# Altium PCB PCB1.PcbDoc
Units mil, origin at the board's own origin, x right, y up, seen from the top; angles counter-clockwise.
Board outline 1968 x 1968 mil, 4 copper layers (Top Layer, Internal Plane 1, Internal Plane 2, Bottom Layer), stack 18.2 mil thick; 11 components, 12 nets, 36 pads, 0 vias.
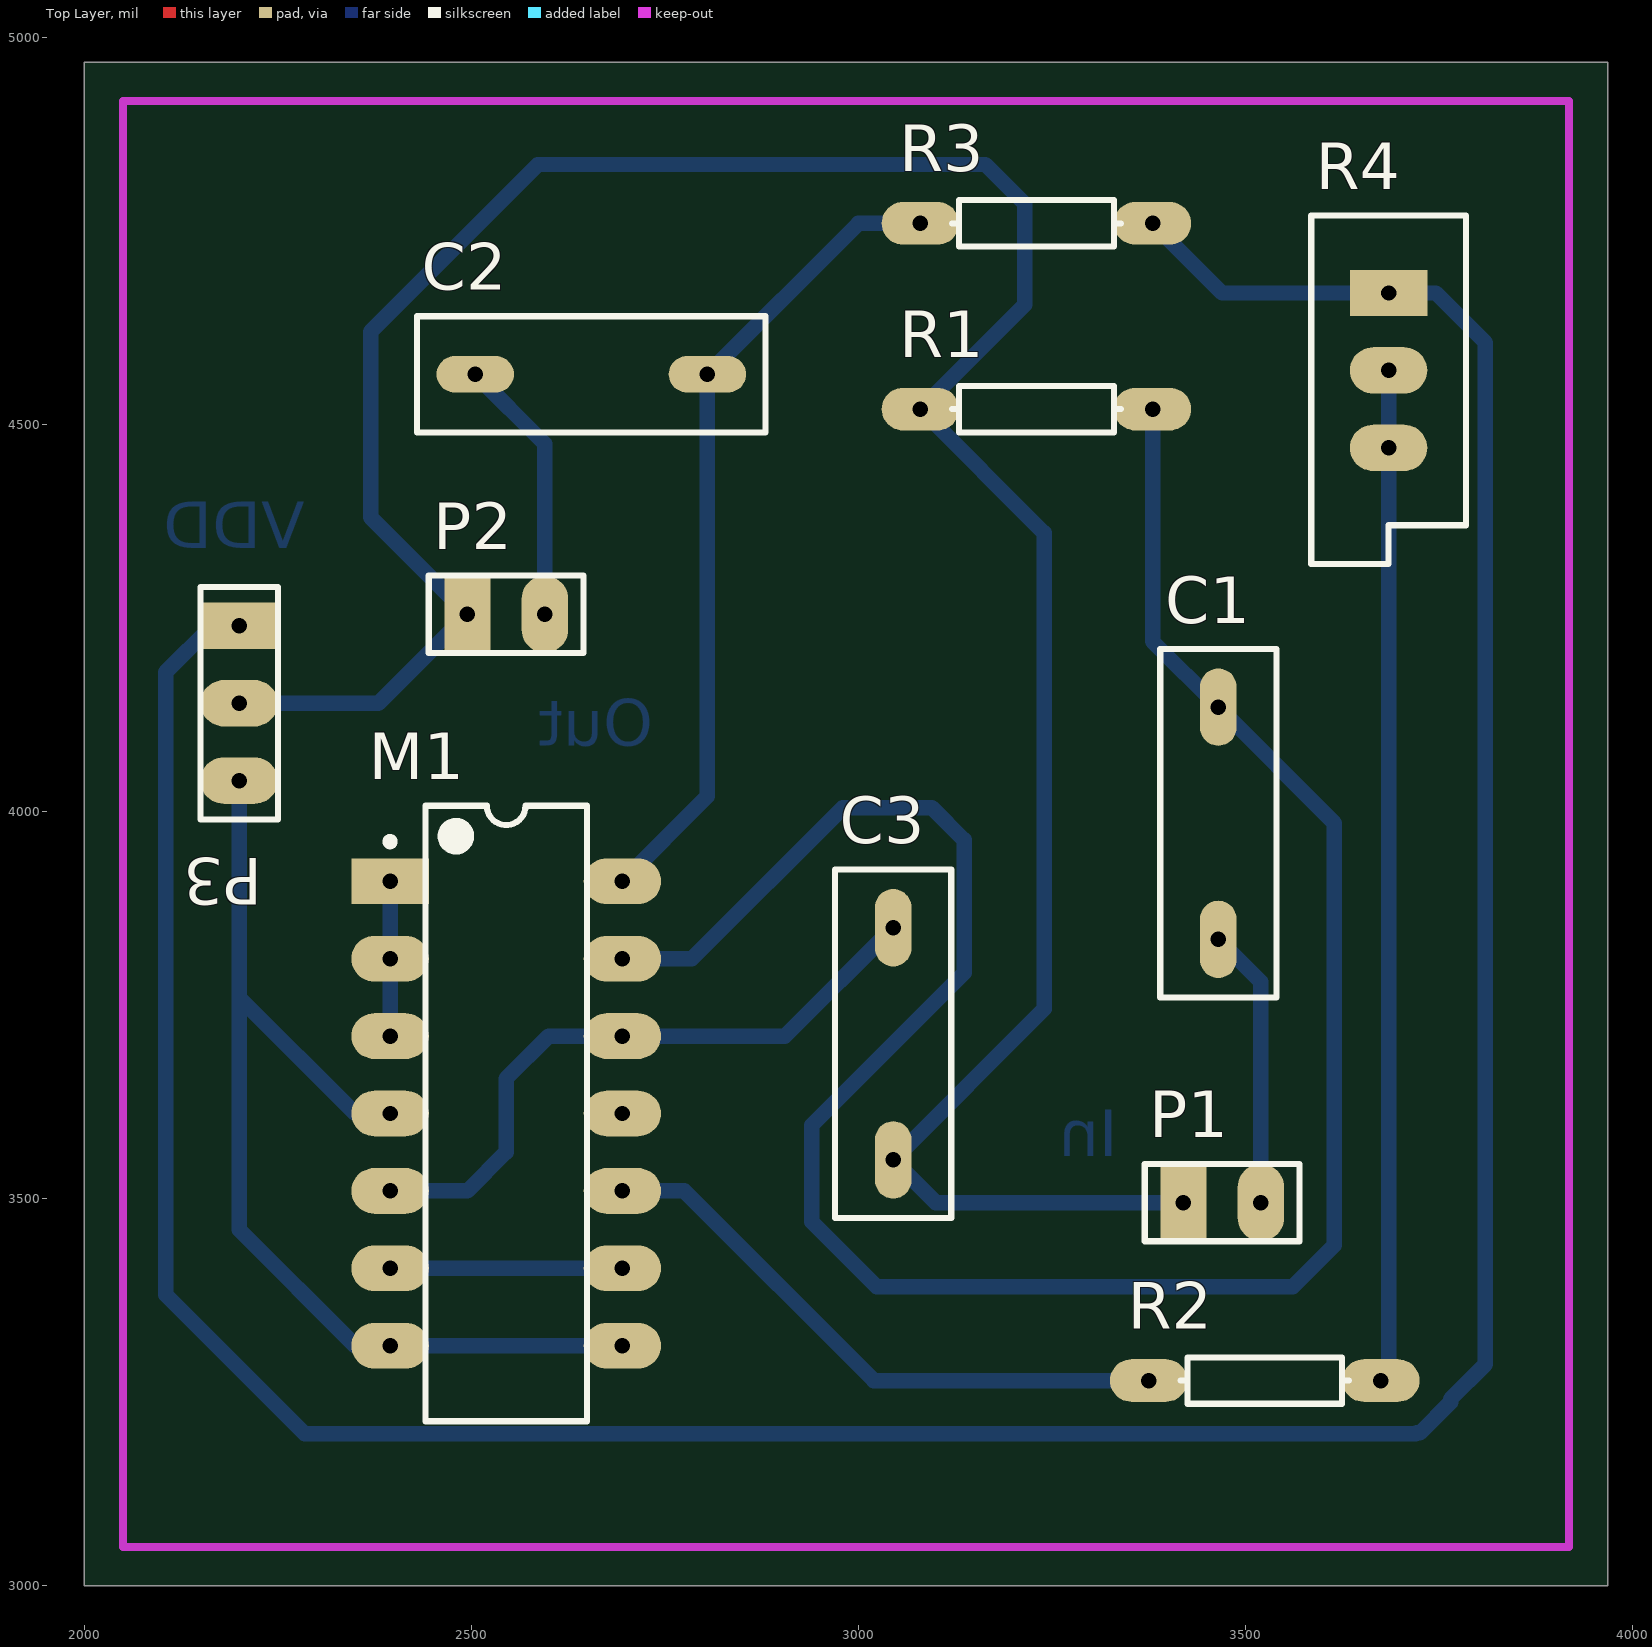
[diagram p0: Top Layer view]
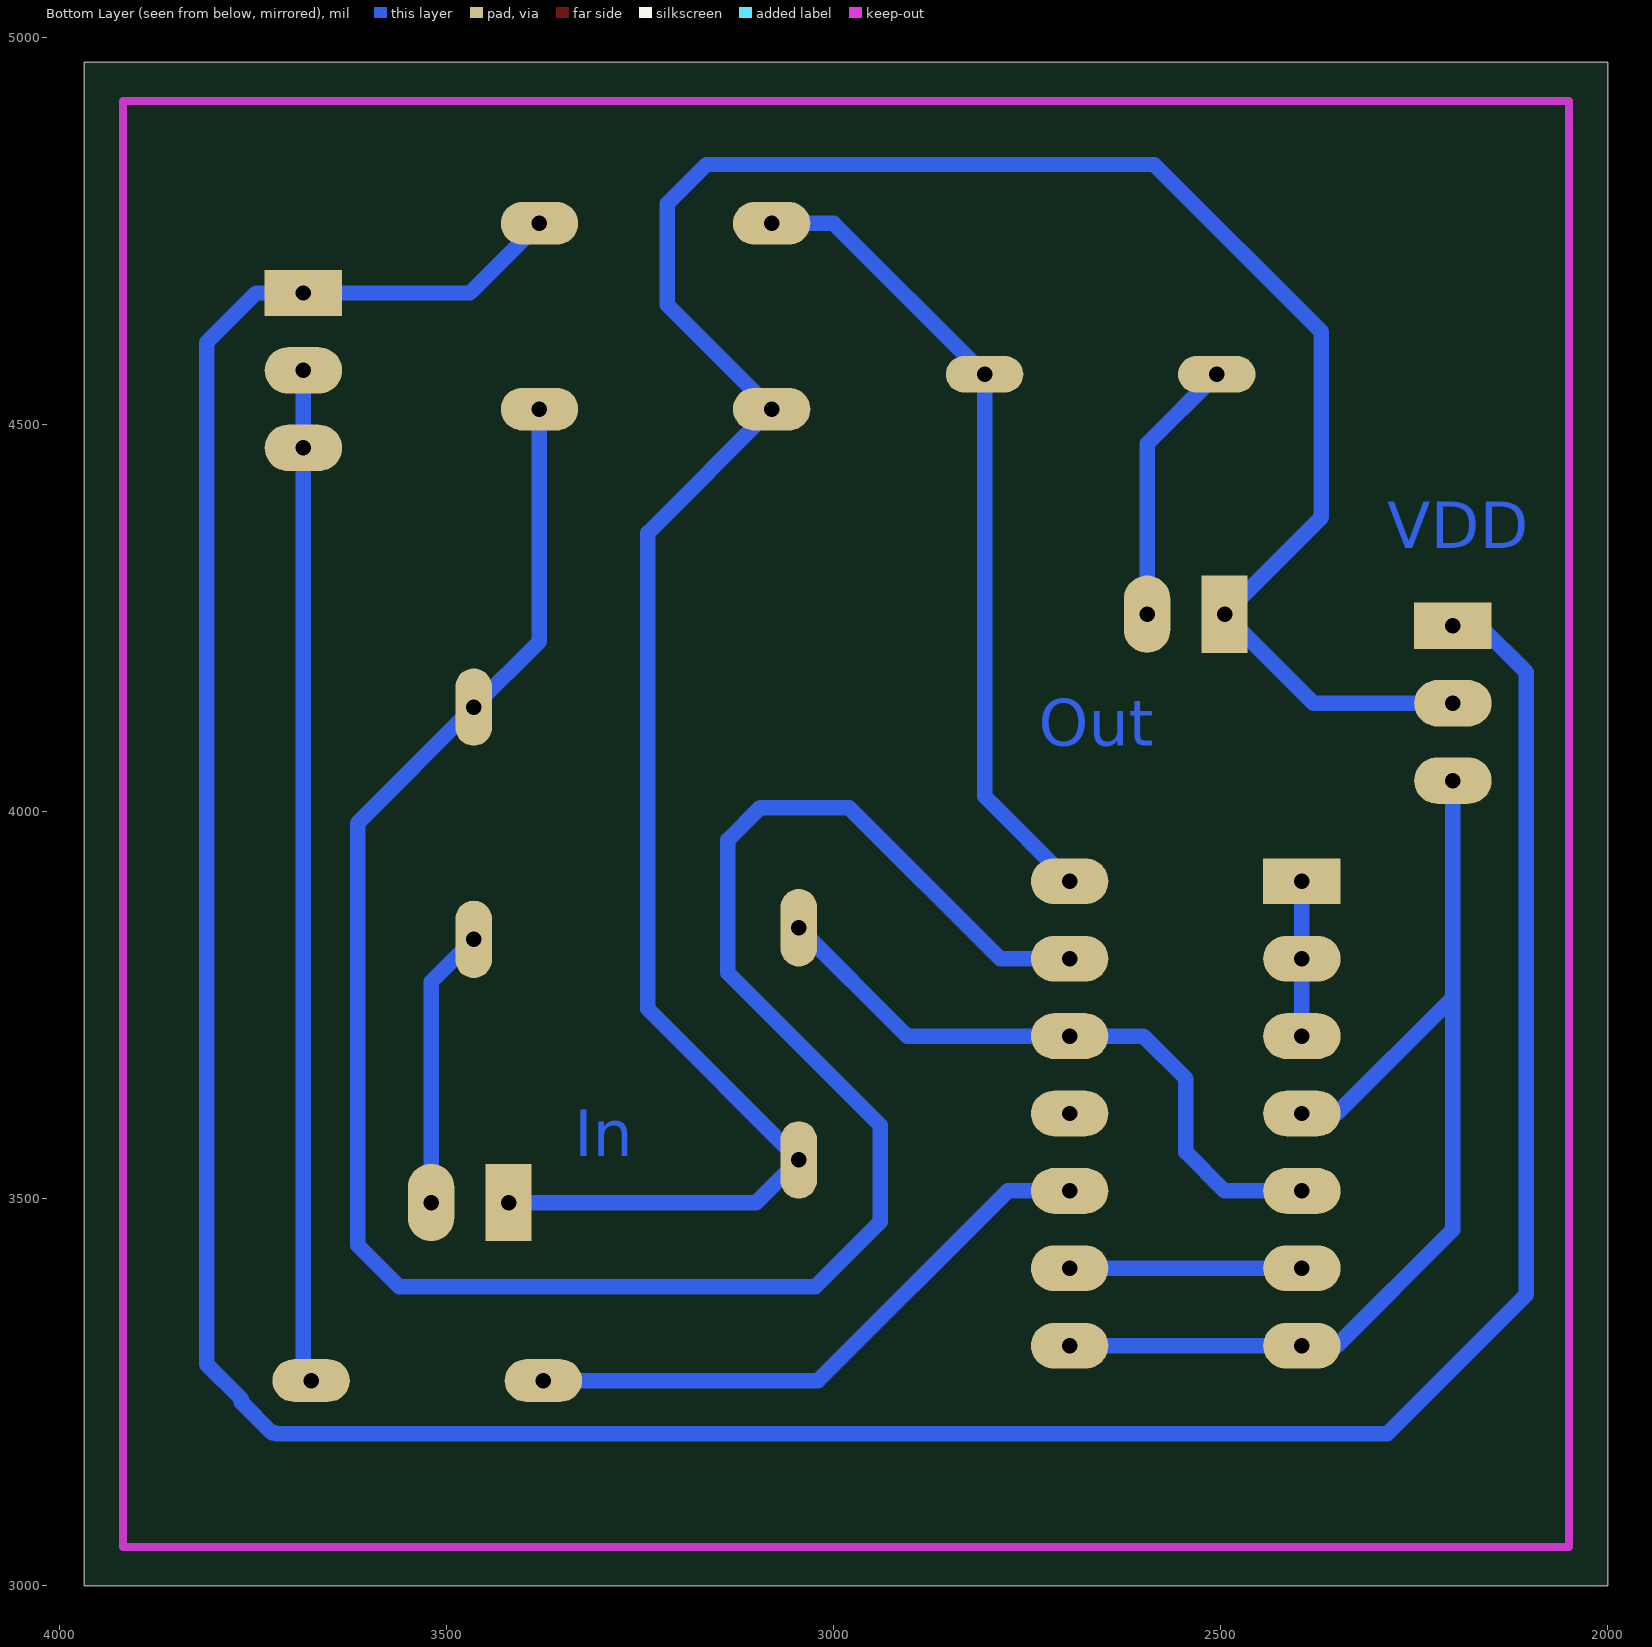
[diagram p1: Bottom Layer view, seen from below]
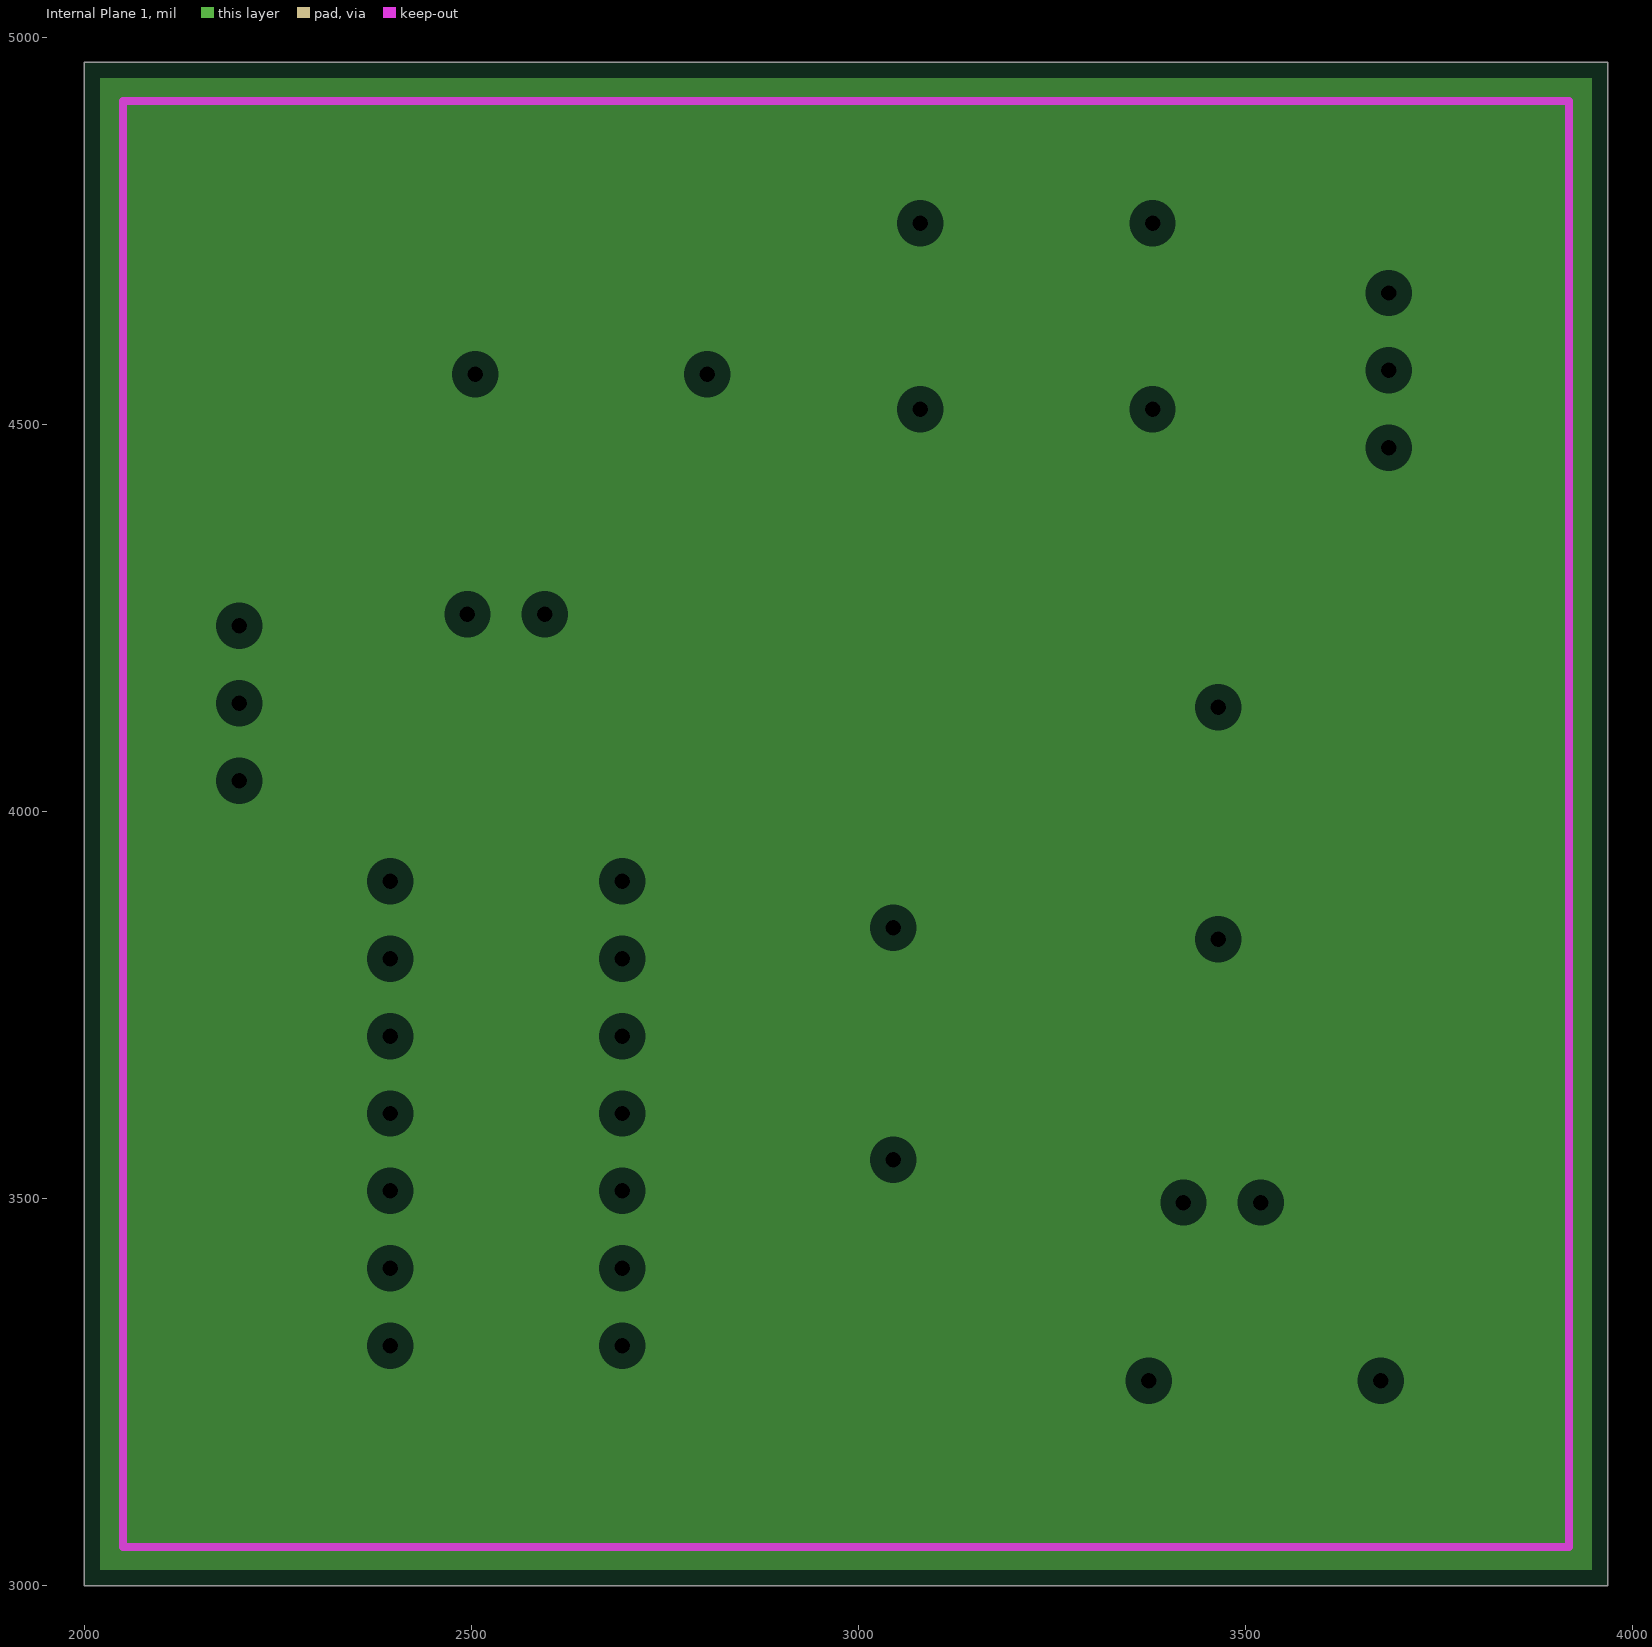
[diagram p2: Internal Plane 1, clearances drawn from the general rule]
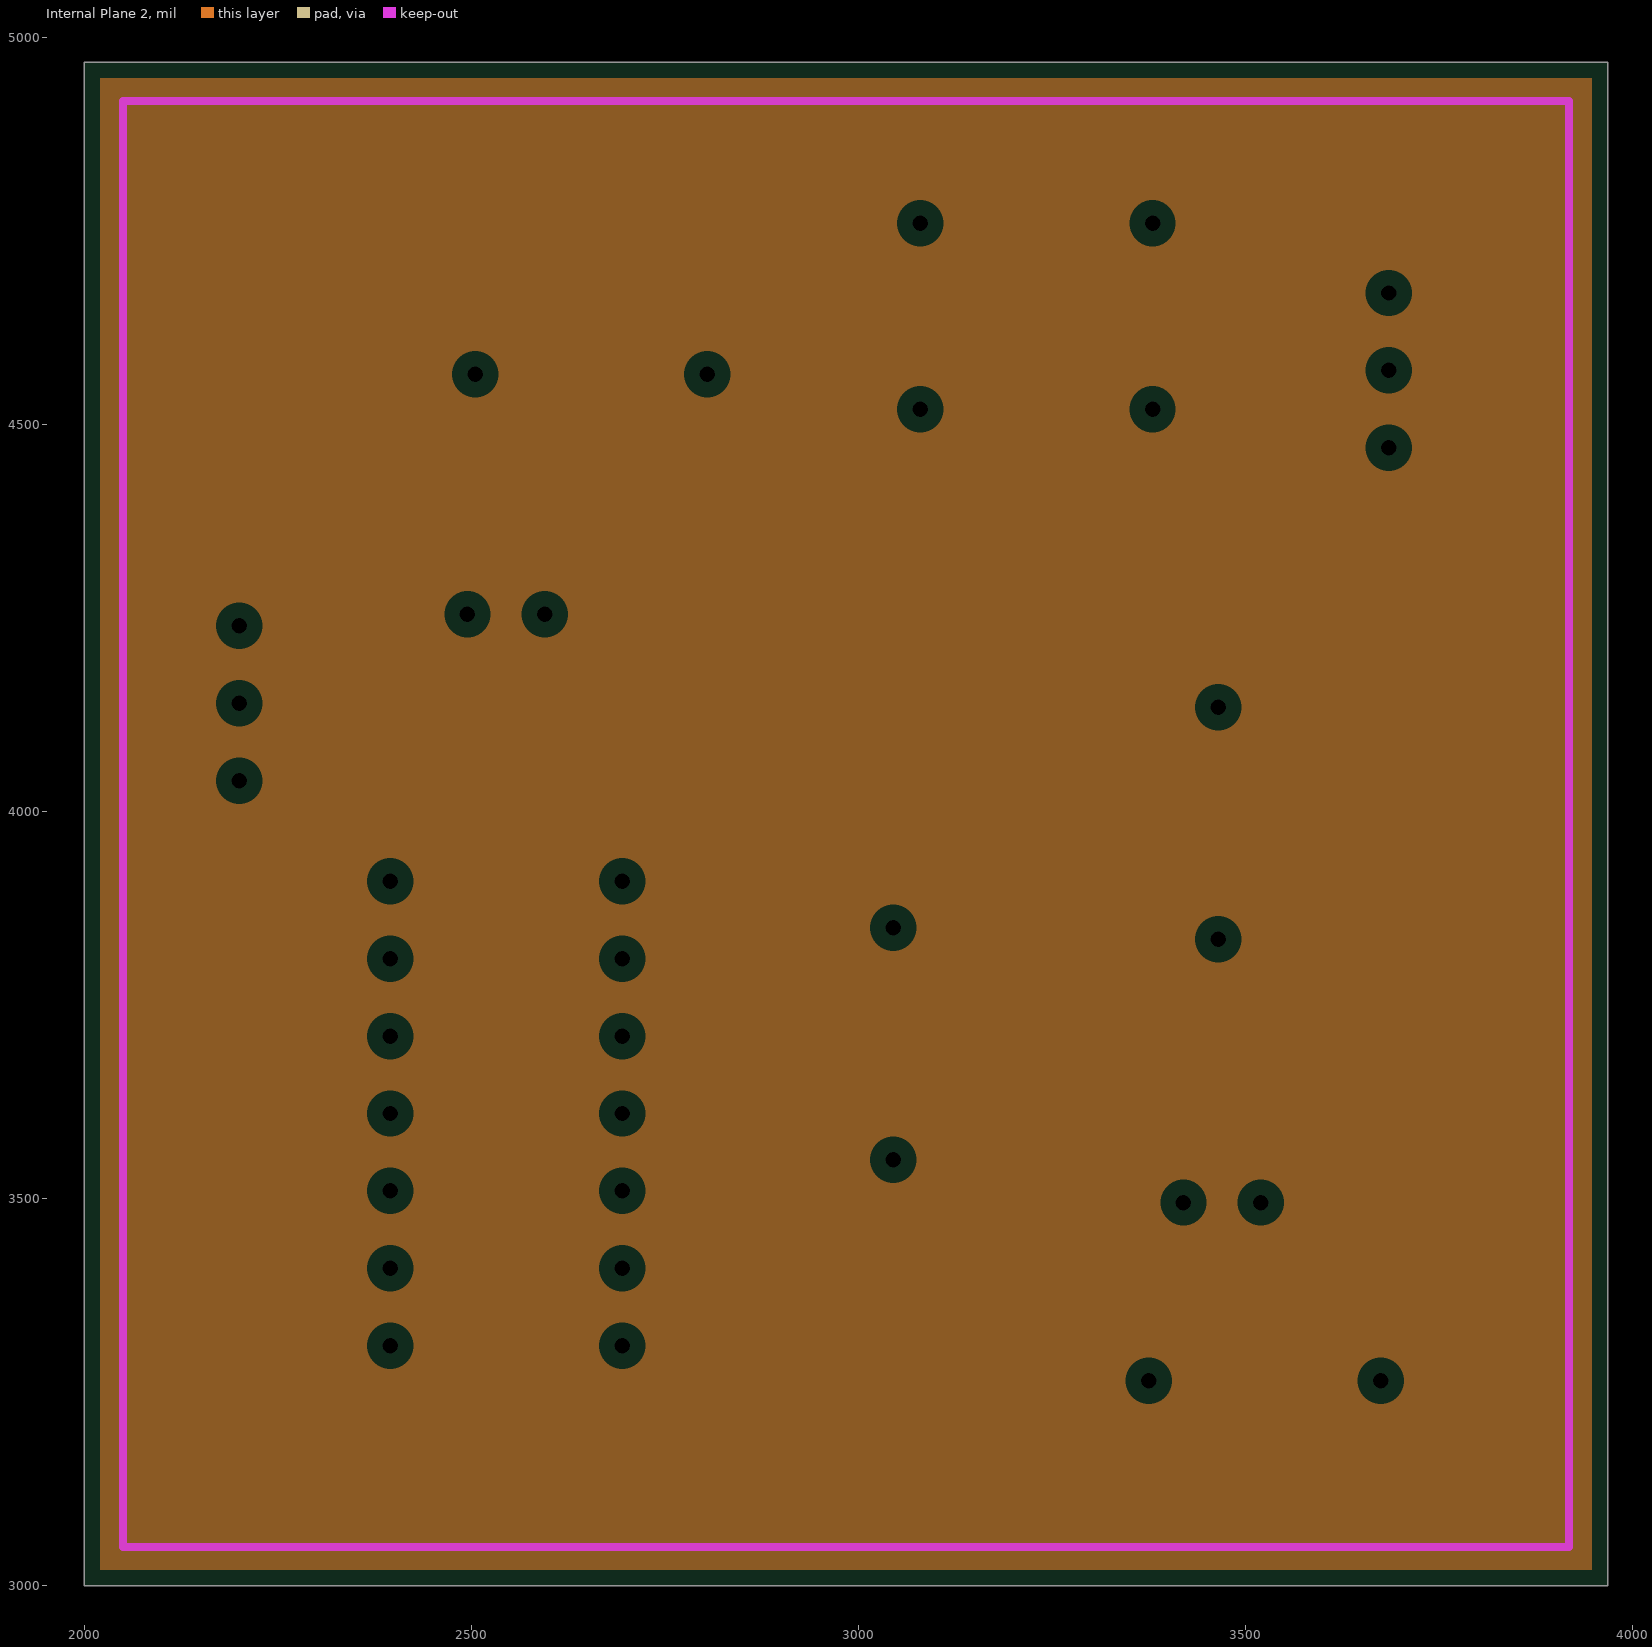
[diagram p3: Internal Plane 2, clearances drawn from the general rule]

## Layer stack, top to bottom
Top Solder: solder mask 0.4, Solder Resist, Dk 3.5
Top Layer: signal copper 1.4
Internal Plane 1: plane copper 1.4
Internal Plane 2: plane copper 1.4
Dielectric 1: dielectric 12.6, FR-4, Dk 4.8
Bottom Layer: signal copper 1.4
Bottom Solder: solder mask 0.4, Solder Resist, Dk 3.5

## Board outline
2000,3000 3968,3000 3968,4968 2000,4968

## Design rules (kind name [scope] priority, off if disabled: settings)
Clearance [All] p1: gap=30
PlaneClearance [All] p1: clearance=20
PlaneConnect [All] p1: planeconnectstyle=Relief reliefexpansion=20 reliefentries=4 reliefconductorwidth=10 reliefairgap=10
PolygonConnect [All] p1: connectstyle=Relief reliefconductorwidth=10 reliefentries=4 polygonreliefangle="90 Angle" airgapwidth=10
RoutingVias [All] p1: holewidth=32 width=62 viastyle="Through Hole" minholewidth=28 minwidth=50 maxholewidth=28 maxwidth=50
SolderMaskExpansion [All] p1: expansion=4
Width [All] p1: maxlimit=20 minlimit=20 preferedwidth=20
28 further rules are at their usual default settings.

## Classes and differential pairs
component class Sheet1: C1 C2 C3 P1 P2 P3 R1 R2 R3 R4

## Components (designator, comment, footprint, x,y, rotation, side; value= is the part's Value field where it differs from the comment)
C1 "Cap" RAD-0.3 3465,3985 r90 top
C2 "Cap" RAD-0.3 2655,4565 r180 top
C3 "Cap" RAD-0.3 3045,3700 r270 top
M1 "ALD1106" DIP-14 2545,3610 r0 top
P1 "Header 2" HDR1X2 3420,3495 r0 top
P2 "Header 2" HDR1X2 2495,4255 r0 top
P3 "Header 3" HDR1X3 2200,4240 r270 top
R1 "Res1" AXIAL-0.3 3230,4520 r0 top
R2 "Res1" AXIAL-0.3 3525,3265 r0 top
R3 "Res1" AXIAL-0.3 3230,4760 r0 top
R4 "RPot" VR5 3685,4570 r270 top

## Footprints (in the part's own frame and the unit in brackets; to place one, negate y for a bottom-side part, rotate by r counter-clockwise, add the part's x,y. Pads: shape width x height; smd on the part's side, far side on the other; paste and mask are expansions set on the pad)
AXIAL-0.3 [mil] "Axial Device, Thru-Hole; 2 Leads; 0.3 in Pin Spacing"
  oval 100x55.12 hole 20: 1(-150,0) 2(150,0)
  silkscreen extent -109,-30 109,30
DIP-14 [mil] "DIP, 14-Pin, Row Spacing 7.62 mm, Pitch 2.54 mm"
  rect 100x59.06 hole 20: 1(-150,300)
  oval 100x59.06 hole 20: 2(-150,200) 3(-150,100) 4(-150,0) 5(-150,-100) 6(-150,-200) 7(-150,-300) 8(150,-300) 9(150,-200) 10(150,-100) 11(150,0) 12(150,100) 13(150,200) 14(150,300)
  silkscreen extent -155,-398 104,398, body extent -142,-398 142,398, height 200
HDR1X2 [mil] "Connector; Header; 2 Position"
  rect 60x100 hole 20: 1(0,0)
  oval 60x100 hole 20: 2(100,0)
  silkscreen extent -50,-50 150,50
HDR1X3 [mil] "Connector; Header; 3 Position"
  rect 60x100 hole 20: 1(0,0)
  oval 60x100 hole 20: 2(100,0) 3(200,0)
  silkscreen extent -50,-50 250,50
RAD-0.3 [mil] "Radial Cap, Thru-Hole; 2 Leads; 0.3 in Pin Spacing"
  oval 100x47.24 hole 20: 1(-150,0) 2(150,0)
  silkscreen extent -225,-75 225,75
VR5 [mil] "Thru-Hole; 3 Leads"
  rect 60x100 hole 20: 1(-100,0)
  oval 60x100 hole 20: 2(0,0) 3(100,0)
  silkscreen extent -200,-100 250,100

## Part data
C1 C2 C3: "Capacitor"
M1: "Quad N-channel matched MOSFET array"
P1 P2: "Header, 2-Pin"
P3: "Header, 3-Pin"
R1 R2 R3: "Resistor"
R4: "Potentiometer"

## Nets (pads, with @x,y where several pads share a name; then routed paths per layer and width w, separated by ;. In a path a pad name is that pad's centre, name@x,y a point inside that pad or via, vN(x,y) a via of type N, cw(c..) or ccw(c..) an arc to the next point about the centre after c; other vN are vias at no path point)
GND: C3.2 P1.1 P2.1 P3.2 R1.1 | length 3550.8
  Bottom Layer w20: P3.2 2380,4140 P2.1 2370,4380 2370,4620 2586,4836 3164,4836 3215,4785 3215,4655 R1.1 3240,4360 3240,3745 C3.2 3100,3495 P1.1
NetC1_1: C1.1 P1.2 | length 362.8
  Bottom Layer w20: C1.1 3520,3780 P1.2
NetC1_2: C1.2 M1.13 R1.2 | length 3024
  Bottom Layer w20: M1.13 2785,3810 2980,4005 3095,4005 3136.62,3963.38 3136.62,3791.62 2940,3595 2940,3470 3024,3386 3561,3386 3615,3440 3615,3985 C1.2 3380,4220 R1.2
NetC2_1: C2.1 M1.14 R3.1 | length 1056.3
  Bottom Layer w20: M1.14 2805,4020 C2.1 3000,4760 R3.1
NetC2_2: C2.2 P2.2 | length 347.3
  Bottom Layer w20: C2.2 2595,4475 P2.2
NetC3_1: C3.1 M1.5 M1.12 | length 846.5
  Bottom Layer w20: M1.5 2495,3510 2545,3560 2545,3655 2600,3710 M1.12 2905,3710 C3.1
NetM1_1: M1.1 M1.2 M1.3 | length 200
  Bottom Layer w20: M1.3 M1.2 M1.1
NetM1_6: M1.6 M1.9 | length 300
  Bottom Layer w20: M1.6 M1.9
NetM1_10: M1.10 R2.1 | length 781.5
  Bottom Layer w20: M1.10 2775,3510 3020,3265 R2.1
NetR2_2: R2.2 R4.2 R4.3 | length 1295
  Bottom Layer w20: R2.2@3685,3275 R4.3 R4.2
VDD: P3.1 R3.2 R4.1 | length 4556.8
  Bottom Layer w20: P3.1 2165,4240 2105,4180 2105,3376 2285,3196 3720,3196 3721.44,3197.44 3725.42,3197.44 3765,3237.02 3765,3241 3810,3286 3810,4606 3746,4670 R4.1 3470,4670 R3.2
VSS: M1.4 M1.7 M1.8 P3.3 | length 1394.3
  Bottom Layer w20: P3.3 2200,3760 ; M1.4 2350,3610 2200,3760 ; M1.8 M1.7 2350,3310 2200,3460 2200,3760
pads on no net: M1.11

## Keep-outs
Keep-Out Layer:
  lines w10: 2050,3050 2050,4918 3918,4918 3918,3050 2050,3050

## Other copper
Bottom Layer:
  text "VDD" at 2285,4340 h60
  text "Out" at 2735,4085 h60
  text "In" at 3335,3555 h60

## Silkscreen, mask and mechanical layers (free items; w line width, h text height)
Drill Drawing:
  text ".LEGEND" at 4168,3200 h60
  text "Drill Drawing." at 4168,3100 h60

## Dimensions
2050,3050 to 2050,4918 on Mechanical 1
2050,3050 to 3918,3050 on Mechanical 1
